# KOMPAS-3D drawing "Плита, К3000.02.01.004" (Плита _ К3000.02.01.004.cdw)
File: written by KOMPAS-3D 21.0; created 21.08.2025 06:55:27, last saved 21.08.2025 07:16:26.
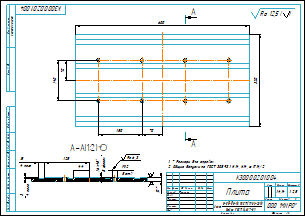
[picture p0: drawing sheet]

Sheet 1: A3, landscape

Document properties: Автор: Lutik; Знак неуказанной шероховатости: 4; Параметр неуказанной шероховатости: Ra 12,5; Масса: 14.141604; Полное имя файла: ..\..\3D\Плита.m3d

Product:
- Part/product: Плита  | designation К3000.02.01.004
    Материал: Лист$dБ-ПН-НО-10 ГОСТ 19903-2015;Ст3сп ГОСТ 14637-89$ (density 7850 kg/m3)
    Масса: 14.141604

Title block, sheet 1: Наименование: Плита; designation: К3000.02.01.004; Материал: Лист Б-ПН-НО-10 ГОСТ 19903-2015 Ст3сп ГОСТ 14637-89; Масса: 14,14; Количество листов документа: 1; organisation: ООО "МИРО"; Форматы листов документа: A3; stored path: C:\Users\Lutik\YandexDisk\Документы\Новая папка\Бабка задняя\2D\Рама_К3000.02.01.000\Плита _ К3000.02.01.004.cdw; Разработал: Тимонин

Views: Вид 1, Сверху, Разрез 2, Разрез А-А
Referenced files in C:\Users\Lutik\YandexDisk\Документы\Новая папка\Бабка задняя\3D\: Плита.m3d
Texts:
  Ra 6,3
  Ra 12,5
  Ra 12,5 ( )
  К3000.02.01.004 Плита
Dimensions and other numbers on the sheet: 600; 320; 70; 150; 140; 44; 125; 15; 4 паза; 3; 10; 12; 8 отв.; 1,6; 8 фасок; 1:2,5; 1; 14,14

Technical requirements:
  * Размеры для справок.
  Общие допуски по ГОСТ 30893.1: Н14, h14, ± IT14/2.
